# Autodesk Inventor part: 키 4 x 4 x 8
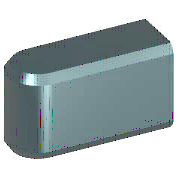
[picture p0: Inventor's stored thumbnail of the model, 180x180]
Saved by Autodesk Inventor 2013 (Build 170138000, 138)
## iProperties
Created: 2012-02
Part Number: 키 4 x 4 x 8
Material: 강철, 연강
Description: 키 및 해당 키홈
Document SubType Name: Modeling
Standard: KS B 1311
Designer: mduedu
Standards Organization: KS
Language: ko-KR
Size Designation: 4 x 4 x 8
Categories: <MemberInstance><Categories><Category DisplayName="샤프트 부품" InternalName="7f7aeb1f-a693-4053-b835-cee3144e0d98" Mnemonic="SHFT"><Category DisplayName="키" Interna
Density: 1 g/cm^3
IsCustomPart: 1
Author: mduedu
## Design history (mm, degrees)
sketch "스케치1"
  geometry: L1 (2, 2)-(8, 2); L2 (8, 2)-(8, -2); L3 (8, -2)-(2, -2); L4 (0, 7)-(0, -7) reference; L5 (-5, 0)-(30, 0) reference; A1 r 2 centre (2, 0) between (2, 2) and (2, -2)
  constraints: 6 end point, 3 tangent, 2 point on circle, 1 centre point, 1 horizontal, 1 parallel, 1 perpendicular, 1 point on line
  dimensions: "d0" = 2 radius of A1 (= 0.5 x PB); "d7" = 8 distance between parallel lines of L2 L4 (= NLG)
workplane "Work Plane1"
workplane "Work Plane2"
extrude "본체1" new body sketch "스케치1" taper "d3" = 0 deg; stored distance "d4" = 10
workaxis "Work Axis1"
workplane "Work Plane4"
body "Solid1"
chamfer "모따기1" distance "d8" = 0.25 (= PHH); stored, may be unused: second distance "d9" = 0.25 (= PHH), angle "d13" = 45 deg
other parameters: "d1" = -2.5 (= -PNT), "d2" = 1.5 (= PH - PNT), "NLG" = 8 [user parameter; used in 2 equation terms], "PB" = 4 [user parameter; used in 1 equation term], "PNT" = 2.5 [user parameter; used in 2 equation terms], "PH" = 4 [user parameter; used in 1 equation term], "PHH" = 0.25 [user parameter; used in 2 equation terms], "d10" = 0, "d16" = 0, "d17" = 0, "d18" = 0, "RR" = 0.08 [user parameter], "WDMAX" = 12 [user parameter], "PLB1" = 8 (= NLG) [user parameter], "PUEB" = 1.8 [user parameter]
